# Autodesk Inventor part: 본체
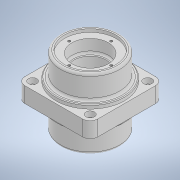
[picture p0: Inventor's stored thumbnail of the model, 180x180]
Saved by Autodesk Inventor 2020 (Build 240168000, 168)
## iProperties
Created: 2023-10
Part Number: 본체
Material: 일반
Document SubType Name: Modeling
Designer: oem
Density: 1 g/cm^3
Appearance: 기본값
Author: oem
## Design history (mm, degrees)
sketch "스케치2"
  geometry: L1 (-47, 47)-(47, 47); L2 (47, 47)-(47, -47); L3 (47, -47)-(-47, -47); L4 (-47, -47)-(-47, 47); L5 (-47, 47)-(47, -47); L6 (47, 47)-(-47, -47); 1 further point
  constraints: 12 end point, 2 midpoint, 2 parallel, 1 horizontal, 1 perpendicular
  dimensions: "d0" = 94 distance between parallel lines of L3 L1; "d1" = 94 distance between parallel lines of L4 L2
extrude "돌출1" new body sketch "스케치2" stored distance "d2" = 20; taper "d3" = 0 deg
sketch "스케치3"
  geometry: C1 r 44 at (0, 0); 1 further point
  constraints: 1 centre point, 1 coincident
  dimensions: "d4" = 88 diameter of C1
extrude "돌출2" join sketch "스케치3" distance "d5" = 5; taper "d6" = 0 deg
sketch "스케치4"
  geometry: C1 r 44 at (0, 0) reference; C2 r 38 at (0, 0)
  constraints: 1 centre point, 1 coincident
  dimensions: "d7" = 76 diameter of C2
extrude "돌출3" join sketch "스케치4" distance "d8" = 30; taper "d9" = 0 deg
sketch "스케치5"
  geometry: C1 r 38 at (0, 0) reference; C2 r 33 at (0, 0)
  constraints: 1 centre point, 1 coincident
  dimensions: "d10" = 66 diameter of C2
extrude "돌출4" cut sketch "스케치5" distance "d11" = 4; taper "d12" = 0 deg
sketch "스케치6"
  geometry: C1 r 33 at (0, 0) reference; C2 r 23.5 at (0, 0)
  constraints: 1 centre point, 1 coincident
  dimensions: "d13" = 47 diameter of C2
extrude "돌출5" cut sketch "스케치6" distance "d14" = 17; taper "d15" = 0 deg
sketch "스케치7"
  geometry: C1 r 23.5 at (0, 0) reference; C2 r 20.5 at (0, 0)
  constraints: 1 centre point, 1 coincident
  dimensions: "d16" = 41 diameter of C2
extrude "돌출6" cut sketch "스케치7" extent not by distance; stored distance "d17" = 17; taper "d18" = 0 deg
sketch "스케치8"
  geometry: C1 r 23.5 at (0, 0) reference; C2 r 23.5 at (0, 0) reference; C3 r 33 at (0, 0) reference; 4 further points
  constraints: 2 horizontal alignment, 2 vertical alignment
  dimensions: "d19" = 54 distance of point (27, 0) point (-27, 0); "d20" = 54 distance of point (0, -27) point (0, 27); "d21" = 27 distance of point (27, 0) C1.centre; "d22" = 27 distance of point (0, -27) C1.centre
hole "구멍1" sketch "스케치8" at (0, 27), (0, -27), (27, 0), (-27, 0) diameter "d23" = 3.242; stored, may be unused: countersink angle "d27" = 90 deg, drill point angle "d29" = 118 deg; dims "d24" = 8, "d25" = 4, "d26" = 2, "d28" = 10
sketch "스케치9"
  geometry: C1 r 7 at (47, -10); 1 further point
  constraints: 1 centre point, 1 coincident
  dimensions: "d30" = 14 diameter of C1
extrude "돌출7" cut sketch "스케치9" distance "d31" = 2; taper "d32" = 0 deg
sketch "스케치10"
  geometry: C1 r 7 at (0, 0) reference; C2 r 3.5 at (0, 0)
  constraints: 1 centre point, 1 coincident
  dimensions: "d33" = 7 diameter of C2
extrude "돌출8" cut sketch "스케치10" distance "d34" = 2; taper "d35" = 0 deg
sketch "스케치11"
  geometry: C1 r 3.5 at (0, 0) reference; 1 further point
  constraints: 1 coincident
hole "구멍2" sketch "스케치11" at (0, 0) diameter "d36" = 4.917; stored, may be unused: countersink angle "d40" = 90 deg, drill point angle "d42" = 118 deg; dims "d37" = 12, "d38" = 4, "d39" = 2, "d41" = 38
fillet "모깎기1" dims "d43" = 10
fillet "모깎기2" dims "d44" = 3
fillet "모깎기3" dims "d45" = 3
chamfer "모따기1" distance "d46" = 1; stored, may be unused: second distance "d47" = 2, angle "d48" = 45 deg
chamfer "모따기2" distance "d49" = 1; stored, may be unused: second distance "d50" = 2, angle "d51" = 45 deg
fillet "모깎기4" dims "d52" = 3
chamfer "모따기3" distance "d53" = 1; stored, may be unused: second distance "d54" = 2, angle "d55" = 45 deg
chamfer "모따기4" distance "d56" = 1; stored, may be unused: second distance "d57" = 2, angle "d58" = 45 deg
sketch "스케치14"
  geometry: C1 r 44 at (0, 0) reference; C2 r 53 at (0, 0); A1 r 10 centre (37, 37) between (47, 37) and (37, 47) reference; A2 r 10 centre (-37, 37) between (-37, 47) and (-47, 37) reference; A3 r 10 centre (-37, -37) between (-47, -37) and (-37, -47) reference; A4 r 10 centre (37, -37) between (37, -47) and (47, -37) reference; 4 further points
  constraints: 5 coincident, 1 centre point
  dimensions: "d59" = 106 diameter of C2
hole "구멍3" sketch "스케치14" at (37, -37), (-37, -37), (37, 37), (-37, 37) diameter "d60" = 11; stored, may be unused: countersink angle "d64" = 90 deg, drill point angle "d66" = 0 deg; dims "d61" = 12, "d62" = 4, "d63" = 2, "d65" = 7
sketch "스케치15"
  geometry: C1 r 5.5 at (0, 0) reference; C2 r 3.3 at (0, 0); 1 further point
  constraints: 1 centre point, 1 coincident
  dimensions: "d67" = 6.6 diameter of C2
extrude "돌출9" cut sketch "스케치15" extent not by distance; stored distance "d68" = 0; taper "d69" = 0 deg
sketch "스케치16"
  geometry: C1 r 5.5 at (0, 0) reference; C2 r 3.3 at (0, 0); 1 further point
  constraints: 1 centre point, 1 coincident
  dimensions: "d70" = 6.6 diameter of C2
extrude "돌출10" cut sketch "스케치16" extent not by distance; stored distance "d71" = 0; taper "d72" = 0 deg
sketch "스케치17"
  geometry: 2 further points
  constraints: 1 other
feature "엠보싱1" sketch "스케치17" dims "d0" = 94, "d1" = 94, "d73" = 0.5, "d74" = 0
node "솔리드1"
mirror "미러1"
mirror "미러2"
mirror "미러3"
mirror "미러4"
mirror "미러5"
mirror "미러6"
node "투영된 루프1"
feature "A9D066F2-1C7D-4E18-AEED-F7BC21143FA4" dims "d60" = 11, "d61" = 12, "d62" = 4, "d63" = 2, "d64" = 90 deg, "d65" = 7, "d66" = 0
